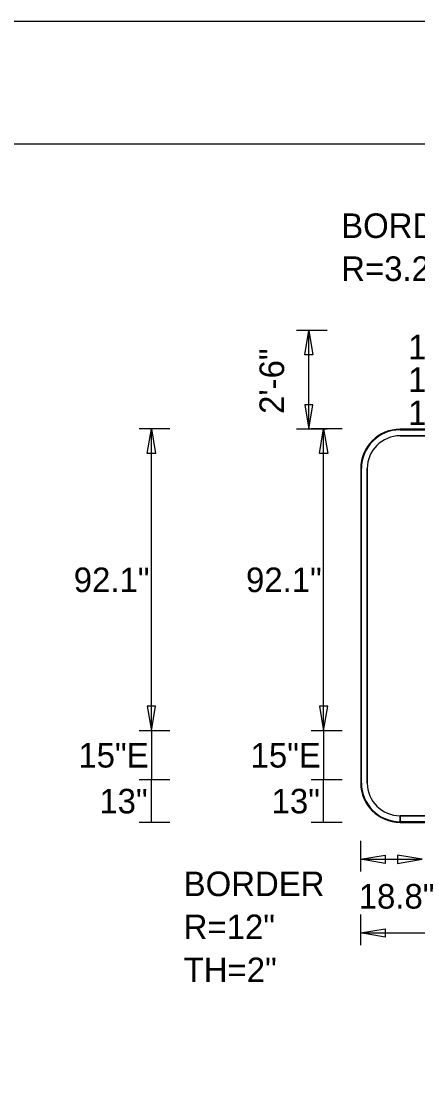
# Model space of a CAD drawing. Extents: x 1806251 to 1809821, y 414895 to 422886.
# Drawn here: x 1809675.75 to 1809676.959, y 415031.001 to 415034.226 of the extents above; entities that cross this region are included whole.
import ezdxf

# ---------------------------------------------------------------- set-up
doc = ezdxf.new("R2010")
doc.units = 0
for name, color, linetype in [('GSBWFILL', 7, 'Continuous'), ('GSCOLORFILL', 7, 'Continuous'), ('GSDIMS', 7, 'Continuous'), ('GSOUTLINE', 7, 'Continuous'), ('GSSHT', 7, 'Continuous')]:
    doc.layers.add(name, color=color, linetype=linetype)

msp = doc.modelspace()

# ---------------------------------------------------------------- linework, layer by layer
at = {"layer": 'GSBWFILL'}
for p, q in [((1809678.2851, 415032.9806), (1809676.9051, 415032.9806)), ((1809676.9051, 415032.9606), (1809678.2851, 415032.9606)), ((1809676.7851, 415032.8606), (1809676.7851, 415031.9006)), ((1809676.8051, 415031.9006), (1809676.8051, 415032.8606)), ((1809676.9051, 415031.7806), (1809676.9051, 415031.8006)), ((1809678.2851, 415031.8006), (1809676.9053, 415031.8006)), ((1809676.9053, 415031.8006), (1809676.9053, 415031.7806)), ((1809676.9053, 415031.7806), (1809678.2851, 415031.7806))]:
    msp.add_line(p, q, dxfattribs=at)
for centre, radius, start, end in [((1809676.9051, 415032.8606), 0.12, 90, 180), ((1809676.9051, 415032.8606), 0.1, 90, 180), ((1809676.9051, 415031.9006), 0.12, 180, 270), ((1809676.9051, 415031.9006), 0.1, 180, 270)]:
    msp.add_arc(centre, radius, start, end, dxfattribs=at)
at = {"layer": 'GSCOLORFILL'}
for p, q in [((1809678.2851, 415032.9806), (1809676.9051, 415032.9806)), ((1809678.2851, 415032.9806), (1809676.9051, 415032.9806)), ((1809678.2851, 415032.9806), (1809676.9051, 415032.9806)), ((1809676.9051, 415032.9786), (1809678.2851, 415032.9786)), ((1809676.9051, 415032.9606), (1809678.2851, 415032.9606)), ((1809676.7851, 415032.8606), (1809676.7851, 415031.9006)), ((1809676.7851, 415032.8606), (1809676.7851, 415031.9006)), ((1809676.7851, 415032.8606), (1809676.7851, 415031.9006)), ((1809676.7871, 415031.9006), (1809676.7871, 415032.8606)), ((1809676.8051, 415031.9006), (1809676.8051, 415032.8606)), ((1809676.9051, 415031.7806), (1809676.9051, 415031.8006)), ((1809676.9051, 415031.7806), (1809676.9051, 415031.7826)), ((1809678.2851, 415031.7826), (1809676.9051, 415031.7826)), ((1809676.9051, 415031.7826), (1809676.9051, 415031.7806)), ((1809676.9051, 415031.7806), (1809678.2851, 415031.7806)), ((1809676.9051, 415031.7806), (1809678.2851, 415031.7806)), ((1809678.2851, 415031.8006), (1809676.9053, 415031.8006)), ((1809676.9053, 415031.8006), (1809676.9053, 415031.7806)), ((1809676.9053, 415031.7806), (1809678.2851, 415031.7806))]:
    msp.add_line(p, q, dxfattribs=at)
for centre, radius, start, end in [((1809676.9051, 415032.8606), 0.12, 90, 180), ((1809676.9051, 415032.8606), 0.12, 90, 180), ((1809676.9051, 415032.8606), 0.12, 90, 180), ((1809676.9051, 415032.8606), 0.118, 90, 180), ((1809676.9051, 415032.8606), 0.1, 90, 180), ((1809676.9051, 415031.9006), 0.12, 180, 270), ((1809676.9051, 415031.9006), 0.12, 180, 270), ((1809676.9051, 415031.9006), 0.12, 180, 270), ((1809676.9051, 415031.9006), 0.118, 180, 270), ((1809676.9051, 415031.9006), 0.1, 180, 270)]:
    msp.add_arc(centre, radius, start, end, dxfattribs=at)
at = {"layer": 'GSDIMS'}
for p, q in [((1809676.6832, 415033.2824), (1809676.5895, 415033.2824)), ((1809676.627, 415032.9804), (1809676.627, 415033.2824)), ((1809676.2032, 415032.9814), (1809676.1095, 415032.9814)), ((1809676.147, 415032.0604), (1809676.147, 415032.9814)), ((1809676.6832, 415032.9804), (1809676.5895, 415032.9804)), ((1809676.7282, 415032.9814), (1809676.6345, 415032.9814)), ((1809676.672, 415032.0604), (1809676.672, 415032.9814)), ((1809676.2032, 415032.0604), (1809676.1095, 415032.0604)), ((1809676.2032, 415032.0604), (1809676.1095, 415032.0604)), ((1809676.147, 415032.0604), (1809676.147, 415031.9104)), ((1809676.7282, 415032.0604), (1809676.6345, 415032.0604)), ((1809676.7282, 415032.0604), (1809676.6345, 415032.0604)), ((1809676.672, 415032.0604), (1809676.672, 415031.9104)), ((1809676.2032, 415031.9104), (1809676.1095, 415031.9104)), ((1809676.2032, 415031.9104), (1809676.1095, 415031.9104)), ((1809676.147, 415031.7804), (1809676.147, 415031.9104)), ((1809676.7282, 415031.9104), (1809676.6345, 415031.9104)), ((1809676.7282, 415031.9104), (1809676.6345, 415031.9104)), ((1809676.672, 415031.7804), (1809676.672, 415031.9104)), ((1809676.2032, 415031.7804), (1809676.1095, 415031.7804)), ((1809676.7282, 415031.7804), (1809676.6345, 415031.7804)), ((1809676.7845, 415031.7241), (1809676.7845, 415031.6304)), ((1809676.7845, 415031.6679), (1809676.9725, 415031.6679)), ((1809676.7845, 415031.4991), (1809676.7845, 415031.4054)), ((1809676.7845, 415031.4429), (1809678.4055, 415031.4429))]:
    msp.add_line(p, q, dxfattribs=at)
for points in [[(1809676.627, 415033.2824), (1809676.6395, 415033.2074), (1809676.6145, 415033.2074)], [(1809676.627, 415032.9804), (1809676.6395, 415033.0554), (1809676.6145, 415033.0554)], [(1809676.147, 415032.9814), (1809676.1595, 415032.9064), (1809676.1345, 415032.9064)], [(1809676.672, 415032.9814), (1809676.6845, 415032.9064), (1809676.6595, 415032.9064)], [(1809676.147, 415032.0604), (1809676.1595, 415032.1354), (1809676.1345, 415032.1354)], [(1809676.672, 415032.0604), (1809676.6845, 415032.1354), (1809676.6595, 415032.1354)], [(1809676.7845, 415031.6679), (1809676.8595, 415031.6804), (1809676.8595, 415031.6554)], [(1809676.9725, 415031.6679), (1809676.8975, 415031.6804), (1809676.8975, 415031.6554)], [(1809676.7845, 415031.4429), (1809676.8595, 415031.4554), (1809676.8595, 415031.4304)]]:
    msp.add_lwpolyline(points, close=True, dxfattribs=at)
at = {"layer": 'GSOUTLINE'}
for p, q in [((1809678.2851, 415032.9806), (1809676.9051, 415032.9806)), ((1809678.2851, 415032.9606), (1809676.9051, 415032.9606)), ((1809676.7851, 415032.8606), (1809676.7851, 415031.9006)), ((1809676.8051, 415032.8606), (1809676.8051, 415031.9006)), ((1809676.9051, 415031.8006), (1809678.2851, 415031.8006)), ((1809676.9051, 415031.7806), (1809678.2851, 415031.7806))]:
    msp.add_line(p, q, dxfattribs=at)
for centre, radius, start, end in [((1809676.9051, 415032.8606), 0.12, 90, 180), ((1809676.9051, 415032.8606), 0.1, 90, 180), ((1809676.9051, 415031.9006), 0.12, 180, 270), ((1809676.9051, 415031.9006), 0.1, 180, 270)]:
    msp.add_arc(centre, radius, start, end, dxfattribs=at)
at = {"layer": 'GSSHT'}
msp.add_line((1809672.1349, 415034.2262), (1809684.8891, 415034.2262), dxfattribs=at)
msp.add_lwpolyline([(1809672.634, 415033.8512), (1809684.6381, 415033.8512), (1809684.6381, 415026.3475), (1809672.634, 415026.3475)], close=True, dxfattribs=at)

# ---------------------------------------------------------------- texts
at = {"layer": 'GSDIMS'}
for s, p in [('BORDER', (1809676.7255, 415033.5644)), ('R=3.25"', (1809676.7255, 415033.4331)), ('10.1"', (1809676.9295, 415033.1941)), ('10"E', (1809676.9295, 415033.0943)), ('10.1"', (1809676.9295, 415032.9931)), ('92.1"', (1809675.9105, 415032.4834)), ('92.1"', (1809676.4355, 415032.4834)), ('15"E', (1809675.9245, 415031.9479)), ('15"E', (1809676.4495, 415031.9479)), ('13"', (1809675.9885, 415031.8079)), ('13"', (1809676.5135, 415031.8079)), ('BORDER', (1809676.2455, 415031.5554)), ('18.8"', (1809676.779, 415031.5174)), ('R=12"', (1809676.2455, 415031.4241)), ('TH=2"', (1809676.2455, 415031.2929))]:
    msp.add_text(s, height=0.075, dxfattribs=at).set_placement(p)
msp.add_text('2\'-6"', height=0.075, rotation=90, dxfattribs=at).set_placement((1809676.5515, 415033.0274))

doc.saveas('drawing.dxf')
